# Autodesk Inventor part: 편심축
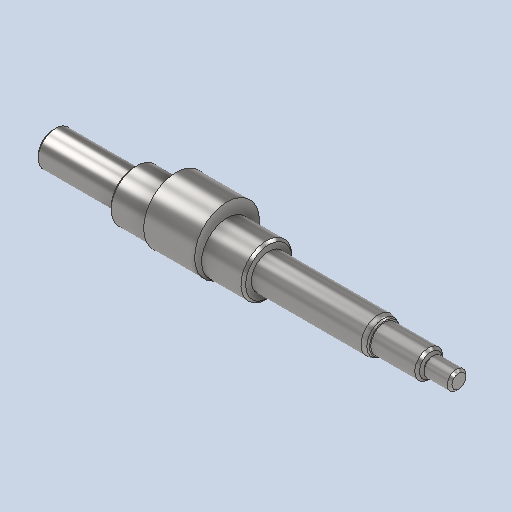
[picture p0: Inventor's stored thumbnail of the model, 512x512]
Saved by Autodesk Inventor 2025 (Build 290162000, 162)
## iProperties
Created: 2024-07
Part Number: 편심축
Material: 강철, 연강
Document SubType Name: Modeling
Designer: samsung
Density: 7.86 g/cm^3
Appearance: 기본값
Author: jhkim
Sending System: Autodesk Inventor 2025
Preprocessor: ST-DEVELOPER v20
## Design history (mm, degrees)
feature "솔리드1"
node "솔리드2"
